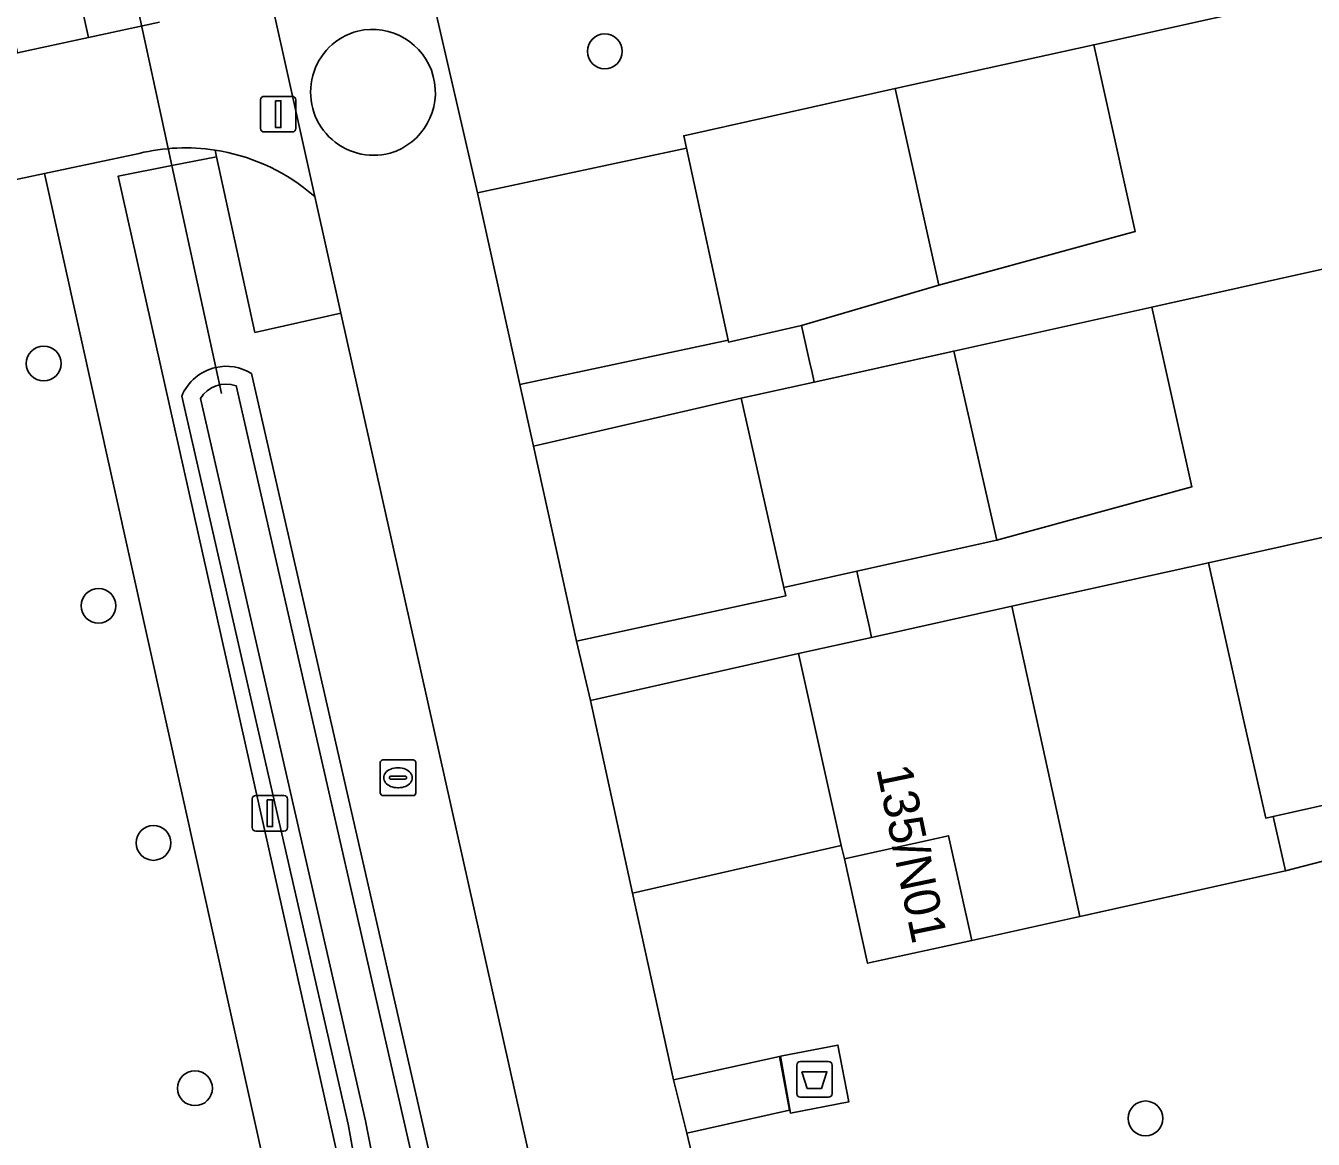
# Model space of a CAD drawing. Extents: x 156661 to 157576, y 383570 to 384425.
# Drawn here: x 156793.83 to 156829.98, y 383910.26 to 383941.52 of the extents above; entities that cross this region are included whole.
import ezdxf

# ---------------------------------------------------------------- set-up
doc = ezdxf.new("R2010")
doc.units = 0
for name, color, linetype in [('IMGEO_Afval_apart_plaats', 7, 'Continuous'), ('IMGEO_Berm_groen', 7, 'Continuous'), ('IMGEO_Boom', 7, 'Continuous'), ('IMGEO_Brandkraan', 7, 'Continuous'), ('IMGEO_Duiker', 7, 'Continuous'), ('IMGEO_Erf', 7, 'Continuous'), ('IMGEO_Groenvoorziening', 7, 'Continuous'), ('IMGEO_Lichtmast', 7, 'Continuous'), ('IMGEO_Muur', 7, 'Continuous'), ('IMGEO_Oever', 7, 'Continuous'), ('IMGEO_Pand', 7, 'Continuous'), ('IMGEO_Pand_nummerreeks', 7, 'Continuous'), ('IMGEO_Parkeervlak_halfverhard', 7, 'Continuous'), ('IMGEO_Parkeervlak_open', 7, 'Continuous'), ('IMGEO_Rijbaan_lokaal_gesloten', 7, 'Continuous'), ('IMGEO_Rijbaan_lokaal_open', 7, 'Continuous'), ('IMGEO_Voetpad_gesloten', 7, 'Continuous'), ('IMGEO_Voetpad_open', 7, 'Continuous'), ('IMGEO_Waterloop', 7, 'Continuous')]:
    doc.layers.add(name, color=color, linetype=linetype)

msp = doc.modelspace()

# ---------------------------------------------------------------- linework, layer by layer
at = {"layer": 'IMGEO_Afval_apart_plaats'}
for p, q in [((156815.482, 383911.541), (156815.482, 383912.341)), ((156815.482, 383912.341), (156815.482, 383911.541)), ((156815.582, 383912.441), (156816.372, 383912.441)), ((156816.372, 383912.441), (156815.582, 383912.441)), ((156816.472, 383912.341), (156816.472, 383911.541)), ((156816.472, 383911.541), (156816.472, 383912.341)), ((156816.372, 383911.441), (156815.582, 383911.441)), ((156815.582, 383911.441), (156816.372, 383911.441))]:
    msp.add_line(p, q, dxfattribs=at)
msp.add_lwpolyline([(156815.625, 383912.155), (156816.329, 383912.155), (156816.18, 383911.685), (156815.774, 383911.685), (156815.625, 383912.155)], dxfattribs=at)
for centre, start, end in [((156815.582, 383912.341), 90, 180), ((156815.582, 383912.341), 90, 180), ((156816.372, 383912.341), 0, 90), ((156816.372, 383912.341), 360, 90), ((156815.582, 383911.541), 180, 270), ((156815.582, 383911.541), 180, 270), ((156816.372, 383911.541), 270, 0), ((156816.372, 383911.541), 270, 0)]:
    msp.add_arc(centre, 0.1, start, end, dxfattribs=at)
at = {"layer": 'IMGEO_Berm_groen'}
for points in [[(156795.637, 383965.148), (156795.252, 383966.882), (156793.102, 383976.569), (156790.698, 383976.013), (156789.615, 383980.975), (156788.201, 383980.63), (156786.905, 383980.313), (156795.59, 383941.189), (156797.583, 383941.621)], [(156802.676, 383933.449), (156800.265, 383932.911), (156799.187, 383937.84), (156797.937, 383937.594), (156796.429, 383937.298), (156803.42, 383906.092), (156803.985, 383904.226)], [(156808.224, 383908.678), (156802.676, 383933.449)], [(156800.168, 383931.757), (156806.348, 383904.688)], [(156802.886, 383910.681), (156798.212, 383931.119)]]:
    msp.add_lwpolyline(points, dxfattribs=at)
for centre, radius, start, end in [((156799.458, 383930.612), 1.346, 102.64, 157.8651), ((156799.461, 383930.617), 1.342, 58.2085, 102.7929), ((156830.582, 383915.192), 28.061, 189.251, 199.5395)]:
    msp.add_arc(centre, radius, start, end, dxfattribs=at)
at = {"layer": 'IMGEO_Boom'}
for centre in [(156810.09, 383940.8), (156794.335, 383932.037), (156795.875, 383925.235), (156797.417, 383918.579), (156798.582, 383911.692), (156825.273, 383910.845)]:
    msp.add_circle(centre, 0.489, dxfattribs=at)
at = {"layer": 'IMGEO_Brandkraan'}
for p, q in [((156803.859, 383920.908), (156804.711, 383920.908)), ((156803.784, 383919.982), (156803.784, 383920.834)), ((156804.272, 383920.688), (156804.297, 383920.688)), ((156804.785, 383920.834), (156804.785, 383919.982)), ((156804.043, 383920.402), (156804.043, 383920.414)), ((156804.481, 383920.365), (156804.083, 383920.365)), ((156804.086, 383920.451), (156804.484, 383920.451)), ((156804.527, 383920.414), (156804.527, 383920.402)), ((156804.711, 383919.908), (156803.859, 383919.908)), ((156804.295, 383920.128), (156804.27, 383920.128))]:
    msp.add_line(p, q, dxfattribs=at)
for points in [[(156803.859, 383920.908), (156804.711, 383920.908)], [(156803.784, 383919.982), (156803.784, 383920.834)], [(156804.785, 383920.834), (156804.785, 383919.982)], [(156804.711, 383919.908), (156803.859, 383919.908)]]:
    msp.add_lwpolyline(points, dxfattribs=at)
for centre, radius, start, end in [((156803.861, 383920.832), 0.0765, 91.552, 178.448), ((156803.861, 383920.832), 0.0765, 91.552, 178.448), ((156804.709, 383920.832), 0.0765, 1.552, 88.448), ((156804.709, 383920.832), 0.0765, 1.552, 88.448), ((156804.083, 383920.411), 0.0403, 85.8775, 175.7526), ((156804.08, 383920.401), 0.0366, 178.938, 274.7102), ((156804.484, 383920.408), 0.043, 264.8664, 352.4533), ((156804.488, 383920.413), 0.0386, 1.7309, 96.639), ((156803.861, 383919.984), 0.0765, 181.552, 268.448), ((156803.861, 383919.984), 0.0765, 181.552, 268.448), ((156804.709, 383919.984), 0.0765, 271.552, 358.448), ((156804.709, 383919.984), 0.0765, 271.552, 358.448)]:
    msp.add_arc(centre, radius, start, end, dxfattribs=at)
for centre, major_axis, ratio, start_param, end_param in [((156804.271, 383920.408), (-0.387, 0.002), 0.722429, 4.712389, 7.853982), ((156804.296, 383920.408), (-0.39, 0.002), 0.717154, 1.570796, 4.712389)]:
    msp.add_ellipse(centre, major_axis=major_axis, ratio=ratio, start_param=start_param, end_param=end_param, dxfattribs=at)
at = {"layer": 'IMGEO_Duiker'}
msp.add_lwpolyline([(156796.083, 383946.154), (156796.25, 383945.383), (156797.626, 383939.03), (156797.937, 383937.594), (156799.164, 383931.925), (156799.323, 383931.192)], dxfattribs=at)
at = {"layer": 'IMGEO_Erf'}
for points in [[(156819.469, 383934.238), (156824.985, 383935.745), (156823.818, 383940.987), (156818.242, 383939.753)], [(156821.097, 383927.076), (156826.57, 383928.572), (156825.454, 383933.622), (156819.89, 383932.386)], [(156828, 383922.163), (156827.04, 383926.444), (156821.518, 383925.224), (156822.464, 383920.921), (156823.434, 383916.512), (156829.202, 383917.794), (156828.862, 383919.324), (156828.648, 383919.276)]]:
    msp.add_lwpolyline(points, close=True, dxfattribs=at)
at = {"layer": 'IMGEO_Groenvoorziening'}
for points in [[(156833.708, 383949.734), (156810.924, 383944.655), (156810.91, 383944.714), (156805.002, 383943.411), (156806.516, 383936.828), (156812.384, 383938.086), (156812.309, 383938.432), (156818.242, 383939.753), (156823.818, 383940.987), (156833.736, 383943.193)], [(156801.01, 383907.365), (156795.487, 383906.115), (156795.088, 383907.896), (156800.623, 383909.14), (156794.353, 383937.37), (156783.169, 383934.99), (156784.232, 383930.211), (156784.555, 383928.753), (156788.41, 383929.644), (156792.818, 383909.646), (156772.807, 383905.13), (156768.321, 383925.155), (156769.229, 383925.367), (156768.136, 383929.92)], [(156820.131, 383898.001), (156834.922, 383910.265), (156833.107, 383918.804), (156829.202, 383917.794), (156823.434, 383916.512), (156820.398, 383915.844), (156817.468, 383915.2), (156816.817, 383918.128), (156816.732, 383918.51), (156810.873, 383917.164), (156812.023, 383911.93), (156814.996, 383912.584), (156815.273, 383911.078), (156812.396, 383910.435), (156812.552, 383909.758)]]:
    msp.add_lwpolyline(points, dxfattribs=at)
msp.add_lwpolyline([(156815.303, 383910.995), (156815.026, 383912.59), (156816.636, 383912.903), (156816.942, 383911.31)], close=True, dxfattribs=at)
at = {"layer": 'IMGEO_Lichtmast'}
for p, q in [((156800.426, 383938.637), (156800.426, 383939.437)), ((156800.426, 383939.437), (156800.426, 383938.637)), ((156800.526, 383939.537), (156801.316, 383939.537)), ((156801.316, 383939.537), (156800.526, 383939.537)), ((156801.416, 383939.437), (156801.416, 383938.637)), ((156801.416, 383938.637), (156801.416, 383939.437)), ((156801.316, 383938.537), (156800.526, 383938.537)), ((156800.526, 383938.537), (156801.316, 383938.537)), ((156800.192, 383919.012), (156800.192, 383919.812)), ((156800.192, 383919.812), (156800.192, 383919.012)), ((156800.292, 383919.912), (156801.082, 383919.912)), ((156801.082, 383919.912), (156800.292, 383919.912)), ((156801.182, 383919.812), (156801.182, 383919.012)), ((156801.182, 383919.012), (156801.182, 383919.812)), ((156801.082, 383918.912), (156800.292, 383918.912)), ((156800.292, 383918.912), (156801.082, 383918.912))]:
    msp.add_line(p, q, dxfattribs=at)
for points in [[(156800.846, 383939.412), (156800.996, 383939.412), (156800.996, 383938.662), (156800.846, 383938.662), (156800.846, 383939.412)], [(156800.612, 383919.787), (156800.762, 383919.787), (156800.762, 383919.037), (156800.612, 383919.037), (156800.612, 383919.787)]]:
    msp.add_lwpolyline(points, dxfattribs=at)
for centre, start, end in [((156800.526, 383939.437), 90, 180), ((156800.526, 383939.437), 90, 180), ((156801.316, 383939.437), 0, 90), ((156801.316, 383939.437), 360, 90), ((156800.526, 383938.637), 180, 270), ((156800.526, 383938.637), 180, 270), ((156801.316, 383938.637), 270, 0), ((156801.316, 383938.637), 270, 0), ((156800.292, 383919.812), 90, 180), ((156800.292, 383919.812), 90, 180), ((156801.082, 383919.812), 0, 90), ((156801.082, 383919.812), 360, 90), ((156800.292, 383919.012), 180, 270), ((156800.292, 383919.012), 180, 270), ((156801.082, 383919.012), 270, 0), ((156801.082, 383919.012), 270, 0)]:
    msp.add_arc(centre, 0.1, start, end, dxfattribs=at)
at = {"layer": 'IMGEO_Muur'}
for points in [[(156818.242, 383939.753), (156823.818, 383940.987)], [(156829.202, 383917.794), (156828.862, 383919.324)], [(156823.434, 383916.512), (156829.202, 383917.794)]]:
    msp.add_lwpolyline(points, dxfattribs=at)
at = {"layer": 'IMGEO_Oever'}
for points in [[(156806.348, 383904.688), (156800.168, 383931.757)], [(156799.737, 383931.416), (156805.872, 383904.543), (156807.334, 383901.215), (156809.099, 383898.036), (156811.151, 383895.035)], [(156798.212, 383931.119), (156802.886, 383910.681)], [(156810.777, 383894.483), (156810.535, 383894.762), (156808.205, 383898.305), (156806.222, 383902.054), (156804.605, 383905.974), (156804.098, 383907.549), (156803.688, 383909.152), (156803.374, 383910.776), (156798.736, 383931.057)]]:
    msp.add_lwpolyline(points, dxfattribs=at)
for centre, radius, start, end in [((156799.458, 383930.612), 1.346, 102.64, 157.8651), ((156799.461, 383930.617), 1.342, 58.2085, 102.7929), ((156799.461, 383930.61), 0.851, 71.088, 148.3719), ((156830.582, 383915.192), 28.061, 189.251, 199.5395)]:
    msp.add_arc(centre, radius, start, end, dxfattribs=at)
at = {"layer": 'IMGEO_Pand'}
for points in [[(156835.377, 383935.827), (156836.733, 383936.134), (156836.622, 383936.62), (156836.586, 383936.783), (156835.23, 383936.476), (156834.15, 383941.33), (156833.955, 383942.205), (156833.736, 383943.193), (156823.818, 383940.987), (156824.985, 383935.745), (156819.469, 383934.238), (156815.612, 383933.105), (156815.84, 383932.096), (156815.91, 383931.788), (156815.972, 383931.515), (156819.89, 383932.386), (156825.454, 383933.622)], [(156815.612, 383933.105), (156819.469, 383934.238), (156818.242, 383939.753), (156812.309, 383938.432), (156812.384, 383938.086), (156813.553, 383932.69), (156813.564, 383932.64)], [(156838.333, 383928.97), (156838.226, 383929.438), (156838.186, 383929.613), (156836.831, 383929.302), (156835.747, 383934.165), (156835.564, 383934.988), (156835.377, 383935.827), (156825.454, 383933.622), (156826.57, 383928.572), (156821.097, 383927.076), (156817.17, 383926.204), (156817.228, 383925.944), (156817.522, 383924.626), (156817.584, 383924.35), (156821.518, 383925.224), (156827.04, 383926.444), (156836.979, 383928.659)], [(156819.89, 383932.386), (156815.972, 383931.515), (156813.922, 383931.06), (156815.119, 383925.748), (156817.17, 383926.204), (156821.097, 383927.076)], [(156837.355, 383926.98), (156837.169, 383927.81), (156836.979, 383928.659), (156827.04, 383926.444), (156828, 383922.163), (156828.648, 383919.276), (156828.862, 383919.324), (156834.083, 383920.486), (156839.933, 383921.788), (156839.83, 383922.252), (156839.787, 383922.442), (156838.44, 383922.142)], [(156822.464, 383920.921), (156821.518, 383925.224), (156817.584, 383924.35), (156815.534, 383923.894), (156816.732, 383918.51), (156816.817, 383918.128), (156819.745, 383918.78), (156820.398, 383915.844), (156823.434, 383916.512)], [(156816.817, 383918.128), (156817.468, 383915.2), (156820.398, 383915.844), (156819.745, 383918.78)]]:
    msp.add_lwpolyline(points, close=True, dxfattribs=at)
at = {"layer": 'IMGEO_Parkeervlak_halfverhard'}
for points in [[(156799.146, 383938.028), (156799.187, 383937.84), (156800.265, 383932.911), (156802.676, 383933.449), (156801.949, 383936.722)], [(156801.949, 383936.722), (156801.775, 383936.87)]]:
    msp.add_lwpolyline(points, dxfattribs=at)
msp.add_arc((156798.31, 383932.566), 5.525, 51.1604, 81.2954, dxfattribs=at)
at = {"layer": 'IMGEO_Parkeervlak_open'}
for points in [[(156812.384, 383938.086), (156806.516, 383936.828), (156807.701, 383931.447), (156813.553, 383932.69)], [(156813.922, 383931.06), (156808.084, 383929.719), (156809.293, 383924.239), (156815.172, 383925.514), (156815.119, 383925.748)], [(156815.534, 383923.894), (156809.69, 383922.576), (156810.873, 383917.164), (156816.732, 383918.51)]]:
    msp.add_lwpolyline(points, close=True, dxfattribs=at)
at = {"layer": 'IMGEO_Rijbaan_lokaal_gesloten'}
for points in [[(156801.775, 383936.87), (156801.949, 383936.722), (156800.028, 383945.365), (156799.984, 383944.824)], [(156797.583, 383941.621), (156795.59, 383941.189), (156793.6, 383940.758), (156762.934, 383934.118)], [(156774.922, 383933.277), (156780.961, 383934.576), (156782.461, 383928.012), (156782.78, 383926.578), (156783.882, 383926.824), (156784.932, 383927.058), (156784.613, 383928.493), (156784.555, 383928.753), (156784.232, 383930.211), (156783.169, 383934.99), (156794.353, 383937.37), (156797.015, 383937.936)]]:
    msp.add_lwpolyline(points, dxfattribs=at)
for centre, radius, start, end in [((156798.314, 383932.576), 5.515, 81.3224, 103.6217), ((156798.31, 383932.566), 5.525, 51.1604, 81.2954)]:
    msp.add_arc(centre, radius, start, end, dxfattribs=at)
at = {"layer": 'IMGEO_Rijbaan_lokaal_open'}
for points in [[(156781.479, 384029.084), (156783.818, 384018.482), (156783.89, 384018.153), (156784.912, 384013.537), (156785.155, 384012.442), (156785.743, 384009.788), (156790.572, 383987.99), (156793.102, 383976.569), (156795.252, 383966.882), (156795.637, 383965.148), (156800.028, 383945.365), (156801.949, 383936.722), (156802.676, 383933.449), (156808.224, 383908.678)], [(156812.552, 383909.758), (156812.396, 383910.435), (156812.023, 383911.93), (156810.873, 383917.164), (156809.69, 383922.576), (156809.293, 383924.239), (156808.084, 383929.719), (156807.701, 383931.447), (156806.516, 383936.828), (156805.002, 383943.411), (156804.664, 383944.993), (156803.456, 383950.473), (156803.072, 383952.198)]]:
    msp.add_lwpolyline(points, dxfattribs=at)
for centre, radius, start, end in [((156803.601, 383939.654), 1.772, 104.6402, 285.0477), ((156803.601, 383939.654), 1.772, 104.6402, 285.0477), ((156803.56, 383939.644), 1.773, 286.4018, 103.2861), ((156803.56, 383939.644), 1.773, 286.4018, 103.2861)]:
    msp.add_arc(centre, radius, start, end, dxfattribs=at)
at = {"layer": 'IMGEO_Voetpad_gesloten'}
msp.add_lwpolyline([(156816.636, 383912.903), (156815.026, 383912.59), (156815.303, 383910.995), (156816.942, 383911.31)], close=True, dxfattribs=at)
at = {"layer": 'IMGEO_Voetpad_open'}
for points in [[(156781.235, 384006.002), (156783.294, 384006.453), (156782.661, 384009.212), (156782.408, 384009.165), (156778.599, 384008.292), (156793.6, 383940.758), (156795.59, 383941.189), (156786.905, 383980.313), (156788.201, 383980.63), (156789.615, 383980.975), (156789.272, 383982.501), (156787.859, 383982.142), (156786.625, 383981.827)], [(156815.972, 383931.515), (156815.91, 383931.788), (156815.84, 383932.096), (156815.612, 383933.105), (156813.564, 383932.64), (156813.553, 383932.69), (156807.701, 383931.447), (156808.084, 383929.719), (156813.922, 383931.06)], [(156817.522, 383924.626), (156817.228, 383925.944), (156817.17, 383926.204), (156815.119, 383925.748), (156815.172, 383925.514), (156809.293, 383924.239), (156809.69, 383922.576), (156815.534, 383923.894), (156817.584, 383924.35)], [(156812.023, 383911.93), (156812.396, 383910.435), (156815.273, 383911.078), (156814.996, 383912.584)]]:
    msp.add_lwpolyline(points, close=True, dxfattribs=at)
for points in [[(156797.015, 383937.936), (156794.353, 383937.37), (156800.623, 383909.14), (156795.088, 383907.896), (156795.487, 383906.115), (156801.01, 383907.365)], [(156796.429, 383937.298), (156797.937, 383937.594), (156799.187, 383937.84), (156799.146, 383938.028)], [(156803.985, 383904.226), (156803.42, 383906.092), (156796.429, 383937.298)], [(156836.719, 383911.755), (156836.167, 383911.298), (156834.083, 383920.486), (156828.862, 383919.324), (156829.202, 383917.794), (156833.107, 383918.804), (156834.922, 383910.265), (156820.131, 383898.001)]]:
    msp.add_lwpolyline(points, dxfattribs=at)
msp.add_arc((156798.314, 383932.576), 5.515, 81.3224, 103.6217, dxfattribs=at)
at = {"layer": 'IMGEO_Waterloop'}
for points in [[(156811.151, 383895.035), (156809.099, 383898.036), (156807.334, 383901.215), (156805.872, 383904.543), (156799.737, 383931.416)], [(156798.736, 383931.057), (156803.374, 383910.776), (156803.688, 383909.152), (156804.098, 383907.549), (156804.605, 383905.974), (156806.222, 383902.054), (156808.205, 383898.305), (156810.535, 383894.762), (156810.777, 383894.483)]]:
    msp.add_lwpolyline(points, dxfattribs=at)
msp.add_arc((156799.461, 383930.61), 0.851, 71.088, 148.3719, dxfattribs=at)

# ---------------------------------------------------------------- texts
at = {"layer": 'IMGEO_Pand_nummerreeks'}
msp.add_text('135/N01', height=1, rotation=281.7344, dxfattribs=at).set_placement((156817.71, 383920.665))

doc.saveas('drawing.dxf')
